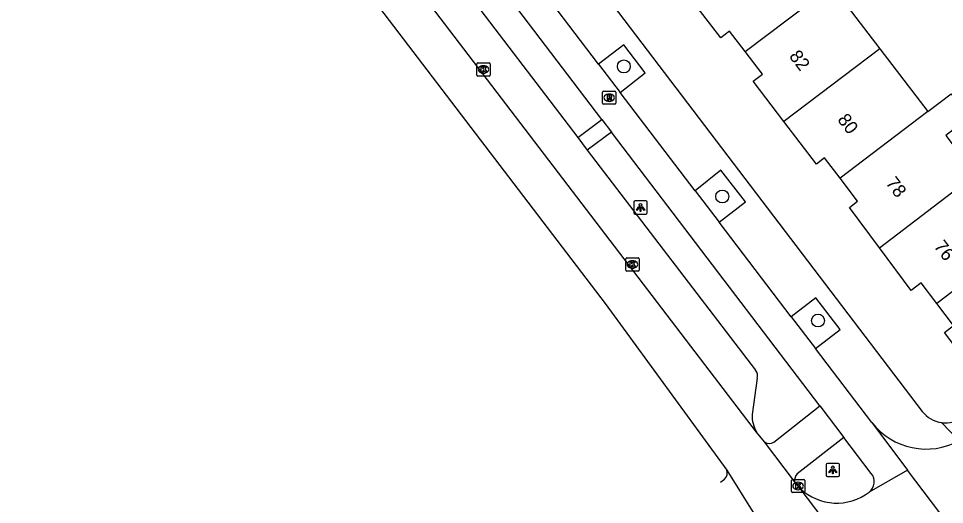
# Model space of a CAD drawing. Extents: x 160037 to 160839, y 385326 to 386441.
# Drawn here: x 160332.7 to 160402.9, y 385621.7 to 385658.5 of the extents above; entities that cross this region are included whole.
import ezdxf

# ---------------------------------------------------------------- set-up
doc = ezdxf.new("R2010")
doc.units = 0
for name, color, linetype in [('IMGEO_Boom', 7, 'Continuous'), ('IMGEO_Fietspad_gesloten', 7, 'Continuous'), ('IMGEO_Kolk', 7, 'Continuous'), ('IMGEO_Lichtpunt', 7, 'Continuous'), ('IMGEO_Pand', 7, 'Continuous'), ('IMGEO_Pand_nummerreeks', 7, 'Continuous'), ('IMGEO_Parkeervlak_open', 7, 'Continuous'), ('IMGEO_Rijbaan_lokaal_gesloten', 7, 'Continuous'), ('IMGEO_Rijbaan_lokaal_open', 7, 'Continuous'), ('IMGEO_Rioolput', 7, 'Continuous'), ('IMGEO_Voetpad_open', 7, 'Continuous')]:
    doc.layers.add(name, color=color, linetype=linetype)

msp = doc.modelspace()

# ---------------------------------------------------------------- linework, layer by layer
at = {"layer": 'IMGEO_Boom'}
for centre in [(160378.564, 385654.88), (160386.019, 385645.02), (160393.273, 385635.618)]:
    msp.add_circle(centre, 0.489, dxfattribs=at)
at = {"layer": 'IMGEO_Fietspad_gesloten'}
for points in [[(160376.889, 385650.857), (160357.654, 385676.185)], [(160376.655, 385655.061), (160371.275, 385662.152)], [(160376.655, 385655.061), (160378.29, 385652.906)], [(160383.977, 385645.439), (160378.29, 385652.906)], [(160376.889, 385650.857), (160377.618, 385649.899)], [(160393.407, 385629.147), (160377.618, 385649.899)], [(160383.977, 385645.439), (160385.777, 385643.076)], [(160391.247, 385635.898), (160385.777, 385643.076)], [(160391.247, 385635.898), (160393.079, 385633.494)], [(160397.346, 385627.892), (160393.079, 385633.494)], [(160393.407, 385629.147), (160395.24, 385626.755)], [(160397.312, 385624.027), (160395.24, 385626.755)]]:
    msp.add_lwpolyline(points, dxfattribs=at)
msp.add_arc((160396.551, 385623.401), 0.985, 307.04083, 39.47833, dxfattribs=at)
at = {"layer": 'IMGEO_Kolk'}
for p, q in [((160367.431, 385654.226), (160367.431, 385655.078)), ((160367.506, 385655.152), (160368.358, 385655.152)), ((160367.919, 385654.932), (160367.944, 385654.932)), ((160368.432, 385655.078), (160368.432, 385654.226)), ((160368.358, 385654.152), (160367.506, 385654.152)), ((160367.942, 385654.372), (160367.917, 385654.372)), ((160378.713, 385639.443), (160378.713, 385640.295)), ((160378.788, 385640.369), (160379.64, 385640.369)), ((160379.201, 385640.149), (160379.226, 385640.149)), ((160379.714, 385640.295), (160379.714, 385639.443)), ((160379.64, 385639.369), (160378.788, 385639.369)), ((160379.224, 385639.589), (160379.199, 385639.589)), ((160391.265, 385622.647), (160391.265, 385623.499)), ((160391.34, 385623.573), (160392.192, 385623.573)), ((160391.753, 385623.353), (160391.778, 385623.353)), ((160392.266, 385623.499), (160392.266, 385622.647)), ((160392.192, 385622.573), (160391.34, 385622.573)), ((160391.776, 385622.793), (160391.751, 385622.793))]:
    msp.add_line(p, q, dxfattribs=at)
for points in [[(160367.431, 385654.226), (160367.431, 385655.078)], [(160367.506, 385655.152), (160368.358, 385655.152)], [(160367.752, 385654.852), (160367.875, 385654.852), (160367.875, 385654.701), (160368.005, 385654.852), (160368.169, 385654.852), (160368.023, 385654.701), (160368.176, 385654.452), (160368.024, 385654.452), (160367.939, 385654.616), (160367.875, 385654.549), (160367.875, 385654.452), (160367.752, 385654.452), (160367.752, 385654.852)], [(160368.432, 385655.078), (160368.432, 385654.226)], [(160368.358, 385654.152), (160367.506, 385654.152)], [(160378.713, 385639.443), (160378.713, 385640.295)], [(160378.788, 385640.369), (160379.64, 385640.369)], [(160379.034, 385640.069), (160379.157, 385640.069), (160379.157, 385639.918), (160379.287, 385640.069), (160379.451, 385640.069), (160379.305, 385639.918), (160379.458, 385639.669), (160379.306, 385639.669), (160379.221, 385639.833), (160379.157, 385639.766), (160379.157, 385639.669), (160379.034, 385639.669), (160379.034, 385640.069)], [(160379.714, 385640.295), (160379.714, 385639.443)], [(160379.64, 385639.369), (160378.788, 385639.369)], [(160391.265, 385622.647), (160391.265, 385623.499)], [(160391.34, 385623.573), (160392.192, 385623.573)], [(160391.586, 385623.273), (160391.709, 385623.273), (160391.709, 385623.122), (160391.839, 385623.273), (160392.003, 385623.273), (160391.857, 385623.122), (160392.01, 385622.873), (160391.858, 385622.873), (160391.773, 385623.037), (160391.709, 385622.97), (160391.709, 385622.873), (160391.586, 385622.873), (160391.586, 385623.273)], [(160392.266, 385623.499), (160392.266, 385622.647)], [(160392.192, 385622.573), (160391.34, 385622.573)]]:
    msp.add_lwpolyline(points, dxfattribs=at)
for centre, start, end in [((160367.508, 385655.076), 91.55205, 178.44795), ((160367.508, 385655.076), 91.55205, 178.44795), ((160368.356, 385655.076), 1.55205, 88.44795), ((160368.356, 385655.076), 1.55205, 88.44795), ((160367.508, 385654.228), 181.55205, 268.44795), ((160367.508, 385654.228), 181.55205, 268.44795), ((160368.356, 385654.228), 271.55205, 358.44795), ((160368.356, 385654.228), 271.55205, 358.44795), ((160378.79, 385640.293), 91.55205, 178.44795), ((160378.79, 385640.293), 91.55205, 178.44795), ((160379.638, 385640.293), 1.55205, 88.44795), ((160379.638, 385640.293), 1.55205, 88.44795), ((160378.79, 385639.445), 181.55205, 268.44795), ((160378.79, 385639.445), 181.55205, 268.44795), ((160379.638, 385639.445), 271.55205, 358.44795), ((160379.638, 385639.445), 271.55205, 358.44795), ((160391.342, 385623.497), 91.55205, 178.44795), ((160391.342, 385623.497), 91.55205, 178.44795), ((160392.19, 385623.497), 1.55205, 88.44795), ((160392.19, 385623.497), 1.55205, 88.44795), ((160391.342, 385622.649), 181.55205, 268.44795), ((160391.342, 385622.649), 181.55205, 268.44795), ((160392.19, 385622.649), 271.55205, 358.44795), ((160392.19, 385622.649), 271.55205, 358.44795)]:
    msp.add_arc(centre, 0.0765, start, end, dxfattribs=at)
for centre, major_axis, ratio, start_param, end_param in [((160367.918, 385654.652), (-0.387, 0.002), 0.722429, 4.712389, 7.853982), ((160367.943, 385654.652), (-0.39, 0.002), 0.717154, 1.570796, 4.712389), ((160379.2, 385639.869), (-0.387, 0.002), 0.722429, 4.712389, 7.853982), ((160379.225, 385639.869), (-0.39, 0.002), 0.717154, 1.570796, 4.712389), ((160391.752, 385623.073), (-0.387, 0.002), 0.722429, 4.712389, 7.853982), ((160391.777, 385623.073), (-0.39, 0.002), 0.717154, 1.570796, 4.712389)]:
    msp.add_ellipse(centre, major_axis=major_axis, ratio=ratio, start_param=start_param, end_param=end_param, dxfattribs=at)
at = {"layer": 'IMGEO_Lichtpunt'}
for p, q in [((160379.332, 385644.593), (160379.332, 385643.786)), ((160379.332, 385644.593), (160379.332, 385643.786)), ((160380.234, 385644.688), (160379.426, 385644.688)), ((160380.234, 385644.688), (160379.426, 385644.688)), ((160380.328, 385643.786), (160380.328, 385644.593)), ((160380.328, 385643.786), (160380.328, 385644.593)), ((160379.426, 385643.692), (160380.234, 385643.692)), ((160379.426, 385643.692), (160380.234, 385643.692)), ((160393.898, 385624.692), (160393.898, 385623.885)), ((160393.898, 385624.692), (160393.898, 385623.885)), ((160394.8, 385624.787), (160393.992, 385624.787)), ((160394.8, 385624.787), (160393.992, 385624.787)), ((160394.894, 385623.885), (160394.894, 385624.692)), ((160394.894, 385623.885), (160394.894, 385624.692)), ((160393.992, 385623.791), (160394.8, 385623.791)), ((160393.992, 385623.791), (160394.8, 385623.791))]:
    msp.add_line(p, q, dxfattribs=at)
for points in [[(160379.706, 385644.257), (160379.745, 385644.229), (160379.557, 385643.967), (160379.519, 385643.994), (160379.706, 385644.257)], [(160379.808, 385644.209), (160379.855, 385644.209), (160379.855, 385643.887), (160379.808, 385643.887), (160379.808, 385644.209)], [(160379.918, 385644.229), (160379.956, 385644.256), (160380.143, 385643.994), (160380.104, 385643.966), (160379.918, 385644.229)], [(160394.272, 385624.356), (160394.311, 385624.328), (160394.123, 385624.066), (160394.085, 385624.093), (160394.272, 385624.356)], [(160394.374, 385624.308), (160394.421, 385624.308), (160394.421, 385623.986), (160394.374, 385623.986), (160394.374, 385624.308)], [(160394.484, 385624.328), (160394.522, 385624.355), (160394.709, 385624.093), (160394.67, 385624.065), (160394.484, 385624.328)]]:
    msp.add_lwpolyline(points, dxfattribs=at)
for centre in [(160379.831, 385644.391), (160394.397, 385624.49)]:
    msp.add_circle(centre, 0.0994, dxfattribs=at)
for centre, start, end in [((160379.426, 385644.593), 90, 180), ((160379.426, 385644.593), 90, 180), ((160380.234, 385644.593), 0, 90), ((160380.234, 385644.593), 0, 90), ((160379.426, 385643.786), 180, 270), ((160379.426, 385643.786), 180, 270), ((160380.234, 385643.786), 270, 0), ((160380.234, 385643.786), 270, 360), ((160393.992, 385624.692), 90, 180), ((160393.992, 385624.692), 90, 180), ((160394.8, 385624.692), 0, 90), ((160394.8, 385624.692), 0, 90), ((160393.992, 385623.885), 180, 270), ((160393.992, 385623.885), 180, 270), ((160394.8, 385623.885), 270, 0), ((160394.8, 385623.885), 270, 360)]:
    msp.add_arc(centre, 0.0946, start, end, dxfattribs=at)
at = {"layer": 'IMGEO_Pand'}
for points in [[(160387.75, 385656.007), (160394.316, 385661.002)], [(160394.316, 385661.002), (160397.949, 385656.227)], [(160387.75, 385656.007), (160386.576, 385657.553), (160385.902, 385657.041), (160383.447, 385660.272)], [(160390.694, 385650.708), (160388.374, 385653.761), (160389.06, 385654.283), (160387.75, 385656.007)], [(160397.949, 385656.227), (160390.694, 385650.708)], [(160397.949, 385656.227), (160401.582, 385651.452)], [(160401.582, 385651.452), (160403.367, 385652.81), (160404.736, 385651.012), (160402.95, 385649.654), (160405.215, 385646.677)], [(160401.582, 385651.452), (160394.949, 385646.406)], [(160394.949, 385646.406), (160393.774, 385647.952), (160393.149, 385647.476), (160390.694, 385650.708)], [(160397.921, 385641.128), (160395.647, 385644.183), (160396.275, 385644.66), (160394.949, 385646.406)], [(160397.921, 385641.128), (160405.215, 385646.677)], [(160408.849, 385641.902), (160402.278, 385636.903)], [(160402.278, 385636.903), (160401.086, 385638.476), (160400.325, 385637.9), (160397.921, 385641.128)], [(160409.605, 385634.586), (160405.98, 385631.84), (160405.805, 385632.07), (160405.195, 385631.608), (160402.844, 385634.71), (160403.54, 385635.237), (160402.278, 385636.903)]]:
    msp.add_lwpolyline(points, dxfattribs=at)
at = {"layer": 'IMGEO_Parkeervlak_open'}
for points in [[(160355.819, 385674.756), (160375.071, 385649.504)], [(160375.797, 385648.527), (160388.532, 385631.843)], [(160388.665, 385631.241), (160388.275, 385628.49)]]:
    msp.add_lwpolyline(points, dxfattribs=at)
for centre, radius, start, end in [((160388.149, 385631.443), 0.554, 338.65688, 46.25962), ((160390.839, 385628.45), 2.565, 179.09637, 210.0326)]:
    msp.add_arc(centre, radius, start, end, dxfattribs=at)
at = {"layer": 'IMGEO_Rijbaan_lokaal_gesloten'}
for points in [[(160332.71, 385695.206), (160377.154, 385636.907), (160386.366, 385624.273)], [(160388.619, 385627.166), (160339.622, 385691.384)], [(160389.227, 385626.413), (160388.619, 385627.166)], [(160391.504, 385623.403), (160389.227, 385626.413)], [(160386.366, 385624.273), (160388.422, 385620.989)], [(160400.065, 385624.282), (160397.145, 385622.614)], [(160403.696, 385619.461), (160400.065, 385624.282)], [(160391.925, 385622.872), (160391.504, 385623.403)], [(160401.444, 385610.367), (160401.35, 385610.462), (160391.925, 385622.872)]]:
    msp.add_lwpolyline(points, dxfattribs=at)
msp.add_arc((160394.686, 385625.79), 4.017, 226.58795, 307.75294, dxfattribs=at)
at = {"layer": 'IMGEO_Rijbaan_lokaal_open'}
msp.add_lwpolyline([(160397.346, 385627.892), (160400.065, 385624.282)], dxfattribs=at)
msp.add_arc((160401.482, 385631.116), 5.244, 217.93482, 298.42374, dxfattribs=at)
at = {"layer": 'IMGEO_Rioolput'}
for p, q in [((160376.955, 385652.085), (160376.955, 385652.937)), ((160377.03, 385653.011), (160377.882, 385653.011)), ((160377.443, 385652.791), (160377.468, 385652.791)), ((160377.956, 385652.937), (160377.956, 385652.085)), ((160377.882, 385652.011), (160377.03, 385652.011)), ((160377.466, 385652.231), (160377.441, 385652.231))]:
    msp.add_line(p, q, dxfattribs=at)
for points in [[(160376.955, 385652.085), (160376.955, 385652.937)], [(160377.03, 385653.011), (160377.882, 385653.011)], [(160377.544, 385652.709), (160377.292, 385652.711), (160377.292, 385652.311)], [(160377.292, 385652.311), (160377.416, 385652.311), (160377.416, 385652.473), (160377.427, 385652.473)], [(160377.47, 385652.63), (160377.416, 385652.63), (160377.416, 385652.549)], [(160377.416, 385652.549), (160377.468, 385652.549)], [(160377.474, 385652.444), (160377.545, 385652.311), (160377.685, 385652.311), (160377.62, 385652.437)], [(160377.956, 385652.937), (160377.956, 385652.085)], [(160377.882, 385652.011), (160377.03, 385652.011)]]:
    msp.add_lwpolyline(points, dxfattribs=at)
for centre, radius, start, end in [((160377.032, 385652.935), 0.0765, 91.55205, 178.44795), ((160377.032, 385652.935), 0.0765, 91.55205, 178.44795), ((160377.426, 385652.42), 0.0533, 26.02933, 88.69889), ((160377.452, 385652.738), 0.19, 274.7715, 282.96867), ((160377.476, 385652.534), 0.0964, 77.00612, 93.18647), ((160377.49, 385652.591), 0.0378, 276.66336, 79.67722), ((160377.543, 385652.599), 0.109, 350.36119, 89.41601), ((160377.541, 385652.599), 0.112, 277.58423, 350.98172), ((160377.525, 385652.384), 0.108, 29.51342, 73.79051), ((160377.88, 385652.935), 0.0765, 1.55205, 88.44795), ((160377.88, 385652.935), 0.0765, 1.55205, 88.44795), ((160377.032, 385652.087), 0.0765, 181.55205, 268.44795), ((160377.032, 385652.087), 0.0765, 181.55205, 268.44795), ((160377.88, 385652.087), 0.0765, 271.55205, 358.44795), ((160377.88, 385652.087), 0.0765, 271.55205, 358.44795)]:
    msp.add_arc(centre, radius, start, end, dxfattribs=at)
for centre, major_axis, ratio, start_param, end_param in [((160377.442, 385652.511), (-0.387, 0.002), 0.722429, 4.712389, 7.853982), ((160377.467, 385652.511), (-0.39, 0.002), 0.717154, 1.570796, 4.712389)]:
    msp.add_ellipse(centre, major_axis=major_axis, ratio=ratio, start_param=start_param, end_param=end_param, dxfattribs=at)
at = {"layer": 'IMGEO_Voetpad_open'}
for points in [[(160339.544, 385709.767), (160401.163, 385628.731)], [(160378.29, 385652.906), (160380.176, 385654.395), (160378.552, 385656.522), (160376.655, 385655.061)], [(160375.071, 385649.504), (160376.889, 385650.857)], [(160377.618, 385649.899), (160375.797, 385648.527)], [(160375.071, 385649.504), (160375.797, 385648.527)], [(160385.777, 385643.076), (160387.785, 385644.61), (160385.913, 385647.022), (160383.977, 385645.439)], [(160393.079, 385633.494), (160394.955, 385634.94), (160393.117, 385637.342), (160391.247, 385635.898)], [(160389.918, 385626.387), (160393.407, 385629.147)], [(160402.635, 385627.874), (160403.978, 385626.504)], [(160395.24, 385626.755), (160391.7, 385624.005)], [(160385.884, 385623.358), (160386.201, 385623.599)]]:
    msp.add_lwpolyline(points, dxfattribs=at)
for centre, radius, start, end in [((160402.934, 385630.08), 2.226, 217.29598, 262.288), ((160402.931, 385630.075), 2.221, 262.34958, 307.45258), ((160389.59, 385626.877), 0.589, 231.91987, 303.77047), ((160385.744, 385624.068), 0.655, 314.25865, 18.2296), ((160392.225, 385623.501), 0.728, 136.19284, 187.73859)]:
    msp.add_arc(centre, radius, start, end, dxfattribs=at)

# ---------------------------------------------------------------- texts
at = {"layer": 'IMGEO_Pand_nummerreeks'}
for s, rotation, p in [('82', 307.25381, (160391.043, 385655.643)), ('80', 307.25381, (160394.701, 385650.834)), ('78', 307.25351, (160398.355, 385646.031)), ('76', 307.25381, (160402.005, 385641.229))]:
    msp.add_text(s, height=1, rotation=rotation, dxfattribs=at).set_placement(p)

doc.saveas('drawing.dxf')
